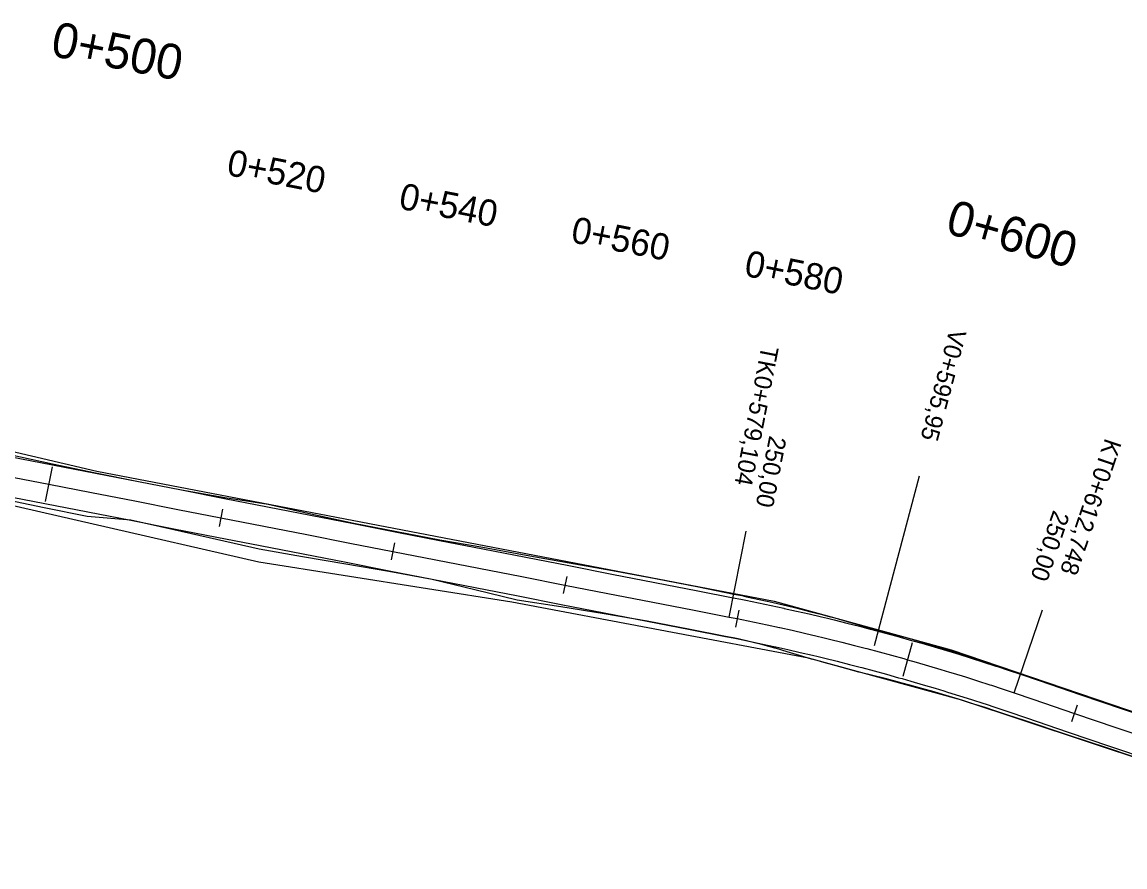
# Model space of a CAD drawing. Extents: x -636600 to -628587, y -1090963 to -1085869.
# Drawn here: x -634765.1 to -634639.3, y -1089450.4 to -1089354 of the extents above; entities that cross this region are included whole.
import ezdxf

# ---------------------------------------------------------------- set-up
doc = ezdxf.new("R2010")
doc.units = 0
for name, color, linetype in [('01_PARCELY_NÁVRH_PC', 7, 'Continuous'), ('HEKTOMETRY100', 7, 'Continuous'), ('HEKTOMETRY20', 7, 'Continuous'), ('HL_BODY', 7, 'Continuous'), ('POLOMERY', 7, 'Continuous'), ('situace_osa', 7, 'Continuous'), ('situace_těleso', 7, 'Continuous'), ('situace_vozovka', 7, 'Continuous'), ('VRCHOLY', 7, 'Continuous')]:
    doc.layers.add(name, color=color, linetype=linetype)

msp = doc.modelspace()

# ---------------------------------------------------------------- linework, layer by layer
at = {"layer": '01_PARCELY_NÁVRH_PC'}
msp.add_lwpolyline([(-634791.48, -1089396.34), (-634786.46, -1089398.22), (-634756.6, -1089405.22), (-634679.35, -1089420.07), (-634659.15, -1089425.61), (-634613.45, -1089441.16), (-634599.95, -1089444.28), (-634600.59, -1089450.37), (-634657.94, -1089431.36), (-634675.44, -1089426.56), (-634709.26, -1089420.16), (-634738.13, -1089415.59), (-634794.85, -1089402.59), (-634792.5, -1089398.61)], close=True, dxfattribs=at)
at = {"layer": 'HEKTOMETRY100'}
for points in [[(-634761.71, -1089404.74), (-634762.48, -1089408.67)], [(-634663.59, -1089424.8), (-634664.68, -1089428.65)]]:
    msp.add_lwpolyline(points, dxfattribs=at)
at = {"layer": 'HEKTOMETRY20'}
for points in [[(-634742.27, -1089409.56), (-634742.66, -1089411.52)], [(-634722.64, -1089413.39), (-634723.03, -1089415.35)], [(-634703.01, -1089417.23), (-634703.4, -1089419.19)], [(-634683.38, -1089421.06), (-634683.77, -1089423.02)], [(-634644.78, -1089431.9), (-634645.42, -1089433.8)]]:
    msp.add_lwpolyline(points, dxfattribs=at)
at = {"layer": 'HL_BODY'}
for points in [[(-634684.46, -1089421.87), (-634682.54, -1089412.05)], [(-634651.97, -1089430.52), (-634648.75, -1089421.05)]]:
    msp.add_lwpolyline(points, dxfattribs=at)
at = {"layer": 'POLOMERY'}
for points in [[(-634684.46, -1089421.87), (-634682.54, -1089412.05)], [(-634651.97, -1089430.52), (-634648.75, -1089421.05)]]:
    msp.add_lwpolyline(points, dxfattribs=at)
at = {"layer": 'situace_osa'}
msp.add_lwpolyline([(-634767, -1089405.75), (-634762.09, -1089406.71), (-634757.19, -1089407.67), (-634752.28, -1089408.62), (-634747.37, -1089409.58), (-634742.46, -1089410.54), (-634737.56, -1089411.5), (-634732.65, -1089412.46), (-634727.74, -1089413.42), (-634722.83, -1089414.37), (-634717.93, -1089415.33), (-634713.02, -1089416.29), (-634708.11, -1089417.25), (-634703.21, -1089418.21), (-634698.3, -1089419.17), (-634693.39, -1089420.12), (-634688.48, -1089421.08), (-634684.46, -1089421.87), (-634683.58, -1089422.04), (-634683.02, -1089422.15), (-634681.59, -1089422.45), (-634680.16, -1089422.75), (-634678.73, -1089423.06), (-634678.68, -1089423.07), (-634677.3, -1089423.37), (-634675.87, -1089423.7), (-634674.45, -1089424.04), (-634673.81, -1089424.19), (-634673.03, -1089424.38), (-634671.61, -1089424.73), (-634670.19, -1089425.09), (-634668.96, -1089425.41), (-634668.77, -1089425.46), (-634667.36, -1089425.83), (-634665.95, -1089426.22), (-634664.54, -1089426.61), (-634664.14, -1089426.73), (-634663.13, -1089427.01), (-634661.73, -1089427.42), (-634660.33, -1089427.84), (-634659.34, -1089428.14), (-634658.93, -1089428.27), (-634657.53, -1089428.7), (-634656.14, -1089429.14), (-634654.74, -1089429.59), (-634654.57, -1089429.65), (-634653.35, -1089430.05), (-634651.97, -1089430.52), (-634649.84, -1089431.24), (-634645.1, -1089432.85), (-634640.37, -1089434.46), (-634635.63, -1089436.06)], dxfattribs=at)
at = {"layer": 'situace_těleso'}
for points in [[(-634766.53, -1089403.32), (-634761.64, -1089404.37), (-634756.74, -1089405.4), (-634751.85, -1089406.41), (-634746.94, -1089407.35), (-634742.01, -1089408.24), (-634737.06, -1089408.98), (-634732.18, -1089410.08), (-634727.3, -1089411.15), (-634722.39, -1089412.1), (-634717.48, -1089413.06), (-634712.56, -1089413.91), (-634707.64, -1089414.81), (-634702.71, -1089415.66), (-634697.79, -1089416.55), (-634692.87, -1089417.47), (-634687.97, -1089418.43), (-634683.94, -1089419.24), (-634683.05, -1089419.42), (-634682.49, -1089419.54), (-634681.05, -1089419.85), (-634679.61, -1089420.17), (-634678.17, -1089420.51), (-634678.12, -1089420.52), (-634676.73, -1089420.86), (-634675.3, -1089421.22), (-634673.87, -1089421.59), (-634673.22, -1089421.76), (-634672.44, -1089421.97), (-634671.01, -1089422.36), (-634669.59, -1089422.77), (-634668.36, -1089423.12), (-634668.17, -1089423.17), (-634666.74, -1089423.54), (-634665.32, -1089423.92), (-634663.89, -1089424.31), (-634663.49, -1089424.43), (-634662.47, -1089424.72), (-634661.05, -1089425.13), (-634659.64, -1089425.56), (-634658.65, -1089425.86), (-634658.23, -1089426), (-634656.82, -1089426.44), (-634655.42, -1089426.9), (-634654.02, -1089427.36), (-634653.85, -1089427.42), (-634652.62, -1089427.83), (-634651.22, -1089428.32), (-634649.09, -1089429.06), (-634644.37, -1089430.7), (-634639.64, -1089432.32), (-634634.91, -1089433.93)], [(-634636.44, -1089438.45), (-634641.19, -1089436.87), (-634645.93, -1089435.29), (-634650.68, -1089433.71), (-634652.81, -1089433), (-634654.19, -1089432.55), (-634655.4, -1089432.16), (-634655.56, -1089432.1), (-634656.94, -1089431.67), (-634658.33, -1089431.24), (-634659.71, -1089430.82), (-634660.12, -1089430.7), (-634661.1, -1089430.41), (-634662.49, -1089430.02), (-634663.89, -1089429.63), (-634664.89, -1089429.36), (-634665.28, -1089429.25), (-634666.68, -1089428.89), (-634668.09, -1089428.54), (-634669.49, -1089428.19), (-634669.68, -1089428.14), (-634670.89, -1089427.8), (-634672.28, -1089427.41), (-634673.68, -1089427.03), (-634674.45, -1089426.83), (-634675.08, -1089426.66), (-634676.46, -1089426.25), (-634677.85, -1089425.82), (-634679.2, -1089425.43), (-634679.25, -1089425.42), (-634680.65, -1089425.04), (-634682.05, -1089424.69), (-634683.47, -1089424.36), (-634684.02, -1089424.25), (-634684.89, -1089424.08), (-634688.92, -1089423.3), (-634693.83, -1089422.35), (-634698.75, -1089421.5), (-634703.69, -1089420.69), (-634708.64, -1089419.93), (-634713.5, -1089418.77), (-634718.37, -1089417.58), (-634723.28, -1089416.66), (-634728.21, -1089415.83), (-634733.14, -1089414.99), (-634738.07, -1089414.11), (-634742.95, -1089413.02), (-634747.83, -1089411.93), (-634752.71, -1089410.83), (-634757.72, -1089410.39), (-634762.62, -1089409.39), (-634767.51, -1089408.36)]]:
    msp.add_lwpolyline(points, dxfattribs=at)
at = {"layer": 'situace_vozovka'}
for points in [[(-634766.57, -1089403.54), (-634761.66, -1089404.5), (-634756.75, -1089405.46), (-634751.85, -1089406.42), (-634746.94, -1089407.37), (-634742.03, -1089408.33), (-634737.13, -1089409.29), (-634732.22, -1089410.25), (-634727.31, -1089411.21), (-634722.4, -1089412.17), (-634717.5, -1089413.12), (-634712.59, -1089414.08), (-634707.68, -1089415.04), (-634702.77, -1089416), (-634697.87, -1089416.96), (-634692.96, -1089417.92), (-634688.05, -1089418.87), (-634684.02, -1089419.66), (-634683.14, -1089419.83), (-634682.58, -1089419.95), (-634681.13, -1089420.24), (-634679.69, -1089420.55), (-634678.24, -1089420.86), (-634678.2, -1089420.87), (-634676.8, -1089421.18), (-634675.36, -1089421.51), (-634673.93, -1089421.85), (-634673.28, -1089422), (-634672.49, -1089422.19), (-634671.06, -1089422.55), (-634669.63, -1089422.91), (-634668.39, -1089423.23), (-634668.2, -1089423.28), (-634666.78, -1089423.66), (-634665.35, -1089424.05), (-634663.93, -1089424.45), (-634663.52, -1089424.56), (-634662.51, -1089424.85), (-634661.09, -1089425.26), (-634659.68, -1089425.68), (-634658.68, -1089425.99), (-634658.27, -1089426.11), (-634656.86, -1089426.55), (-634655.45, -1089427), (-634654.05, -1089427.45), (-634653.87, -1089427.51), (-634652.64, -1089427.91), (-634651.24, -1089428.39), (-634649.11, -1089429.11), (-634644.38, -1089430.72), (-634639.64, -1089432.33), (-634634.91, -1089433.93)], [(-634767.43, -1089407.96), (-634762.52, -1089408.92), (-634757.62, -1089409.87), (-634752.71, -1089410.83), (-634747.8, -1089411.79), (-634742.9, -1089412.75), (-634737.99, -1089413.71), (-634733.08, -1089414.67), (-634728.17, -1089415.62), (-634723.27, -1089416.58), (-634718.36, -1089417.54), (-634713.45, -1089418.5), (-634708.54, -1089419.46), (-634703.64, -1089420.42), (-634698.73, -1089421.37), (-634693.82, -1089422.33), (-634688.91, -1089423.29), (-634684.89, -1089424.08), (-634684.02, -1089424.25), (-634683.47, -1089424.36), (-634682.04, -1089424.65), (-634680.63, -1089424.95), (-634679.21, -1089425.25), (-634679.17, -1089425.26), (-634677.79, -1089425.57), (-634676.38, -1089425.89), (-634674.97, -1089426.22), (-634674.34, -1089426.38), (-634673.56, -1089426.56), (-634672.15, -1089426.91), (-634670.75, -1089427.27), (-634669.53, -1089427.59), (-634669.35, -1089427.63), (-634667.95, -1089428.01), (-634666.55, -1089428.39), (-634665.15, -1089428.78), (-634664.75, -1089428.89), (-634663.76, -1089429.17), (-634662.36, -1089429.58), (-634660.98, -1089429.99), (-634660, -1089430.29), (-634659.59, -1089430.42), (-634658.2, -1089430.85), (-634656.82, -1089431.28), (-634655.44, -1089431.73), (-634655.28, -1089431.78), (-634654.07, -1089432.18), (-634652.69, -1089432.65), (-634650.56, -1089433.37), (-634645.83, -1089434.98), (-634641.09, -1089436.59), (-634636.36, -1089438.19)]]:
    msp.add_lwpolyline(points, dxfattribs=at)
at = {"layer": 'VRCHOLY'}
msp.add_lwpolyline([(-634667.92, -1089425.1), (-634662.78, -1089405.77)], dxfattribs=at)

# ---------------------------------------------------------------- texts
at = {"layer": 'HEKTOMETRY100'}
for s, rotation, p in [('0+500', 348.95, (-634762, -1089357.82)), ('0+600', 344.1609, (-634659.96, -1089378.02))]:
    msp.add_text(s, height=4, rotation=rotation, dxfattribs=at).set_placement(p)
at = {"layer": 'HEKTOMETRY20'}
for s, rotation, p in [('0+520', 348.95, (-634741.91, -1089371.42)), ('0+540', 348.95, (-634722.28, -1089375.25)), ('0+560', 348.95, (-634702.65, -1089379.09)), ('0+580', 348.7446, (-634682.88, -1089382.92))]:
    msp.add_text(s, height=3, rotation=rotation, dxfattribs=at).set_placement(p)
at = {"layer": 'HL_BODY'}
for s, rotation, p in [('TK0+579,104', 258.95, (-634680.78, -1089390.83)), ('KT0+612,748', 251.2394, (-634641.58, -1089401.37))]:
    msp.add_text(s, height=2, rotation=rotation, dxfattribs=at).set_placement(p)
at = {"layer": 'POLOMERY'}
for rotation, p in [(258.95, (-634679.89, -1089401.1)), (251.2394, (-634647.5, -1089409.58))]:
    msp.add_text('250,00', height=2, rotation=rotation, dxfattribs=at).set_placement(p)
at = {"layer": 'VRCHOLY'}
msp.add_text('V0+595,95', height=2, rotation=255.0947, dxfattribs=at).set_placement((-634659.32, -1089388.88))

doc.saveas('drawing.dxf')
